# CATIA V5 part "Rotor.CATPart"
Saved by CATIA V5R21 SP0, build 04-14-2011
Part number: Rotor
Definition: Rotor
Nomenclature: Rotor
Source: Unknown
Bounding box of the stored display mesh (mm): x -0.5 to 0.5, y 0 to 18.6, z -0.5 to 0.5
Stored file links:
  C:\Users\beatr\OneDrive\Documents\UNB\2026_1\Pi1\Componentes eletronicos\Rotor.CATPart
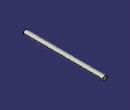
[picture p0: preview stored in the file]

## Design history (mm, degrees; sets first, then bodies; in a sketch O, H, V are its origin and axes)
Body1 "Sólido1" (main body)
  Solid1: solid without history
